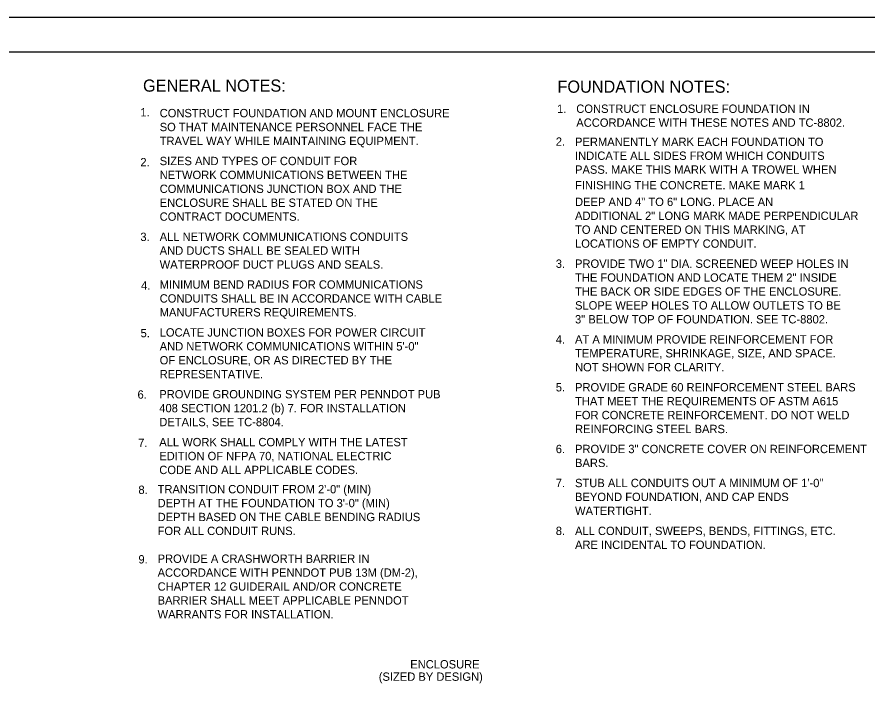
# Model space of a CAD drawing. Extents: x 1299104.8 to 1299141.6, y 239639.8 to 239661.8.
# Drawn here: x 1299117.69 to 1299129.92, y 239652.18 to 239661.79 of the extents above; entities that cross this region are included whole.
import ezdxf

# ---------------------------------------------------------------- set-up
doc = ezdxf.new("R2010")
doc.units = 0
for name, color, linetype in [('GS_plotshape_p', 7, 'Continuous'), ('Level 1', 7, 'Continuous'), ('PTEXT', 7, 'Continuous')]:
    doc.layers.add(name, color=color, linetype=linetype)

msp = doc.modelspace()

# ---------------------------------------------------------------- linework, layer by layer
at = {"layer": 'GS_plotshape_p'}
msp.add_lwpolyline([(1299104.802, 239661.791), (1299138.802, 239661.791), (1299138.802, 239639.791), (1299104.802, 239639.791)], close=True, dxfattribs=at)
at = {"layer": 'Level 1'}
msp.add_lwpolyline([(1299138.302, 239640.291), (1299106.302, 239640.291), (1299106.302, 239661.291), (1299138.302, 239661.291)], close=True, dxfattribs=at)

# ---------------------------------------------------------------- texts
at = {"layer": 'PTEXT'}
for s, height, p in [('GENERAL NOTES:', 0.175, (1299119.504, 239660.717)), ('FOUNDATION NOTES:', 0.175, (1299125.469, 239660.702)), ('1.', 0.12, (1299125.463, 239660.412)), ('CONSTRUCT ENCLOSURE FOUNDATION IN ', 0.12, (1299125.74, 239660.412)), ('1.', 0.12, (1299119.466, 239660.361)), ('CONSTRUCT FOUNDATION AND MOUNT ENCLOSURE ', 0.12, (1299119.744, 239660.349)), ('ACCORDANCE WITH THESE NOTES AND TC-8802.', 0.12, (1299125.74, 239660.212)), ('SO THAT MAINTENANCE PERSONNEL FACE THE ', 0.12, (1299119.744, 239660.149)), ('TRAVEL WAY WHILE MAINTAINING EQUIPMENT.', 0.12, (1299119.744, 239659.949)), ('2.', 0.12, (1299125.445, 239659.939)), ('PERMANENTLY MARK EACH FOUNDATION TO ', 0.12, (1299125.722, 239659.936)), ('INDICATE ALL SIDES FROM WHICH CONDUITS ', 0.12, (1299125.722, 239659.736)), ('2.', 0.12, (1299119.466, 239659.643)), ('SIZES AND TYPES OF CONDUIT FOR ', 0.12, (1299119.744, 239659.66)), ('NETWORK COMMUNICATIONS BETWEEN THE ', 0.12, (1299119.744, 239659.46)), ('PASS. MAKE THIS MARK WITH A TROWEL WHEN ', 0.12, (1299125.722, 239659.536)), ('FINISHING THE CONCRETE. MAKE MARK 1', 0.12, (1299125.722, 239659.312)), ('COMMUNICATIONS JUNCTION BOX AND THE ', 0.12, (1299119.744, 239659.26)), ('DEEP AND 4" TO 6" LONG. PLACE AN ', 0.12, (1299125.722, 239659.072)), ('ENCLOSURE SHALL BE STATED ON THE ', 0.12, (1299119.744, 239659.06)), ('CONTRACT DOCUMENTS.', 0.12, (1299119.744, 239658.86)), ('ADDITIONAL 2" LONG MARK MADE PERPENDICULAR ', 0.12, (1299125.722, 239658.872)), ('TO AND CENTERED ON THIS MARKING, AT ', 0.12, (1299125.722, 239658.672)), ('3.', 0.12, (1299119.466, 239658.569)), ('ALL NETWORK COMMUNICATIONS CONDUITS ', 0.12, (1299119.744, 239658.571)), ('LOCATIONS OF EMPTY CONDUIT.', 0.12, (1299125.722, 239658.472)), ('AND DUCTS SHALL BE SEALED WITH ', 0.12, (1299119.744, 239658.371)), ('WATERPROOF DUCT PLUGS AND SEALS.', 0.12, (1299119.744, 239658.171)), ('3.', 0.12, (1299125.445, 239658.183)), ('PROVIDE TWO 1" DIA. SCREENED WEEP HOLES IN ', 0.12, (1299125.722, 239658.183)), ('THE FOUNDATION AND LOCATE THEM 2" INSIDE ', 0.12, (1299125.722, 239657.983)), ('4.', 0.12, (1299119.476, 239657.87)), ('MINIMUM BEND RADIUS FOR COMMUNICATIONS ', 0.12, (1299119.744, 239657.883)), ('THE BACK OR SIDE EDGES OF THE ENCLOSURE. ', 0.12, (1299125.722, 239657.783)), ('CONDUITS SHALL BE IN ACCORDANCE WITH CABLE ', 0.12, (1299119.744, 239657.683)), ('MANUFACTURERS REQUIREMENTS.', 0.12, (1299119.744, 239657.483)), ('SLOPE WEEP HOLES TO ALLOW OUTLETS TO BE ', 0.12, (1299125.722, 239657.583)), ('3" BELOW TOP OF FOUNDATION. SEE TC-8802.', 0.12, (1299125.722, 239657.383)), ('5.', 0.12, (1299119.469, 239657.184)), ('LOCATE JUNCTION BOXES FOR POWER CIRCUIT ', 0.12, (1299119.744, 239657.194)), ('AND NETWORK COMMUNICATIONS WITHIN 5\'-0" ', 0.12, (1299119.744, 239656.994)), ('4.', 0.12, (1299125.445, 239657.094)), ('AT A MINIMUM PROVIDE REINFORCEMENT FOR ', 0.12, (1299125.722, 239657.094)), ('TEMPERATURE, SHRINKAGE, SIZE, AND SPACE. ', 0.12, (1299125.722, 239656.894)), ('OF ENCLOSURE, OR AS DIRECTED BY THE ', 0.12, (1299119.744, 239656.794)), ('NOT SHOWN FOR CLARITY.', 0.12, (1299125.722, 239656.694)), ('REPRESENTATIVE.', 0.12, (1299119.744, 239656.594)), ('5.', 0.12, (1299125.445, 239656.405)), ('PROVIDE GRADE 60 REINFORCEMENT STEEL BARS ', 0.12, (1299125.722, 239656.405)), ('6.', 0.12, (1299119.425, 239656.301)), ('PROVIDE GROUNDING SYSTEM PER PENNDOT PUB ', 0.12, (1299119.738, 239656.305)), ('THAT MEET THE REQUIREMENTS OF ASTM A615 ', 0.12, (1299125.722, 239656.205)), ('408 SECTION 1201.2 (b) 7. FOR INSTALLATION ', 0.12, (1299119.738, 239656.105)), ('FOR CONCRETE REINFORCEMENT. DO NOT WELD ', 0.12, (1299125.722, 239656.005)), ('DETAILS, SEE TC-8804.', 0.12, (1299119.738, 239655.905)), ('REINFORCING STEEL BARS.', 0.12, (1299125.722, 239655.805)), ('7.', 0.12, (1299119.435, 239655.606)), ('ALL WORK SHALL COMPLY WITH THE LATEST ', 0.12, (1299119.738, 239655.616)), ('6.', 0.12, (1299125.445, 239655.517)), ('PROVIDE 3" CONCRETE COVER ON REINFORCEMENT ', 0.12, (1299125.722, 239655.517)), ('EDITION OF NFPA 70, NATIONAL ELECTRIC ', 0.12, (1299119.738, 239655.416)), ('BARS.', 0.12, (1299125.722, 239655.317)), ('CODE AND ALL APPLICABLE CODES. ', 0.12, (1299119.738, 239655.216)), ('STUB ALL CONDUITS OUT A MINIMUM OF 1\'-0" ', 0.12, (1299125.722, 239655.028)), ('8.', 0.12, (1299119.438, 239654.93)), ('TRANSITION CONDUIT FROM 2\'-0" (MIN) ', 0.12, (1299119.714, 239654.939)), ('7.', 0.12, (1299125.445, 239655.028)), ('BEYOND FOUNDATION, AND CAP ENDS   ', 0.12, (1299125.722, 239654.828)), ('DEPTH AT THE FOUNDATION TO 3\'-0" (MIN)', 0.12, (1299119.714, 239654.739)), ('DEPTH BASED ON THE CABLE BENDING RADIUS ', 0.12, (1299119.714, 239654.539)), ('WATERTIGHT.', 0.12, (1299125.722, 239654.628)), ('FOR ALL CONDUIT RUNS.', 0.12, (1299119.714, 239654.339)), ('8.', 0.12, (1299125.445, 239654.339)), ('ALL CONDUIT, SWEEPS, BENDS, FITTINGS, ETC. ', 0.12, (1299125.722, 239654.339)), ('ARE INCIDENTAL TO FOUNDATION.', 0.12, (1299125.722, 239654.139)), ('9.', 0.12, (1299119.438, 239653.93)), ('PROVIDE A CRASHWORTH BARRIER IN ', 0.12, (1299119.714, 239653.939)), ('ACCORDANCE WITH PENNDOT PUB 13M (DM-2), ', 0.12, (1299119.714, 239653.739)), ('CHAPTER 12 GUIDERAIL AND/OR CONCRETE ', 0.12, (1299119.714, 239653.539)), ('BARRIER SHALL MEET APPLICABLE PENNDOT ', 0.12, (1299119.714, 239653.339)), ('WARRANTS FOR INSTALLATION.', 0.12, (1299119.714, 239653.139)), ('ENCLOSURE', 0.12, (1299123.35, 239652.42)), ('(SIZED BY DESIGN)', 0.12, (1299122.897, 239652.242))]:
    msp.add_text(s, height=height, dxfattribs=at).set_placement(p)

doc.saveas('drawing.dxf')
